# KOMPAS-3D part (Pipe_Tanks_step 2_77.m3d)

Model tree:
1. X Axis
2. Y Axis
3. Z Axis  (labels: Bend 90 Dn 50; Pipe Dn 50)
     Òîëùèíà ñòåíêè 1 = 1

Referenced files in C:\Documents and Settings\kashirsky\Мои документы\Camtasia Studio\Pipelines3D\Tanks\: Tanks_step 2.a3d
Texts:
  Pipe Dn 50
  Steel ASTM A295
  Three Point Plane
  Plane at Angle
  Line and Point Plane
  Axis through Two Vertices
  Axis of Feature
  Axis of Conical Surface
  Axis through Edge
  Trim by Surface
  Trim by Sketch
  Feature with No History
  Intersection Axis of Two Planes
  Two Line Plane
  Line and Face Plane
  Bend by line
  Hole in sheet body
  Cut in sheet body
  Point in CM
  Linear Dimension from Line to Point
  Surface Finish Symbol
  Geometric Tolerance Symbol
  Leader #1
  Leader #2
  Leader #3
  Shape Deviations and Datum
  Node point number
  Mark of coordination axis
  Node point designation
  Mark/Reference designation with leader
  Mark/reference designation on line
  Mark/Reference designation without leader
  Bend 90 Dn 50
  Plane of section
